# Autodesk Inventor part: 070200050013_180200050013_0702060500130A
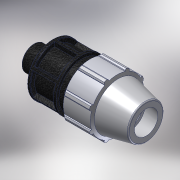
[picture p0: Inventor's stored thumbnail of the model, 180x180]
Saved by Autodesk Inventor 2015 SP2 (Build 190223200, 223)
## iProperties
Created: 2017-02
Part Number: 070200050013_180200050013_0702060500130A
Material: PVC-Piping
Description: PLASSON MALE ADAPTOR 50-1.1/4"
Document SubType Name: Modeling
Designer: KIM
Mass: 92.6774 g
Surface Area: 199.44 cm^2
Volume: 66.1981 cm^3
Density: 1.4 g/cm^3
Appearance: PTFE
Author: KIM
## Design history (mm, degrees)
derived "07020.ipt"
feature "Solid1::07020.ipt"
tag "TaggingFeature1"
body "Solid1"
other parameters: "d4" = 19.42857, "d5" = 34, "d7" = 96, "d8" = 72, "d9" = 19.42857, "d11" = 3.88571, "d12" = 76.8, "d13" = 120 deg, "d14" = 75, "d15" = 8 deg, "d16" = 86.4, "d18" = 2.5, "d19" = 35 deg, "d20" = 17.5 deg, "d21" = 89.28, "d23" = 0, "d25" = 360 deg, "d27" = 1.92, "d34" = 4.8, "d36" = 0, "d42" = 34, "d43" = 2.88, "d46" = 1.5, "d49" = 106, "d51" = 136, "d52" = 22, "d53" = 1, "d55" = 360 deg, "d57" = 41.91, "d58" = 29.337, "d59" = 27.2, "E_" = 96, "H_" = 136, "l_" = 106, "l_2" = 22, "R_" = 41.91
